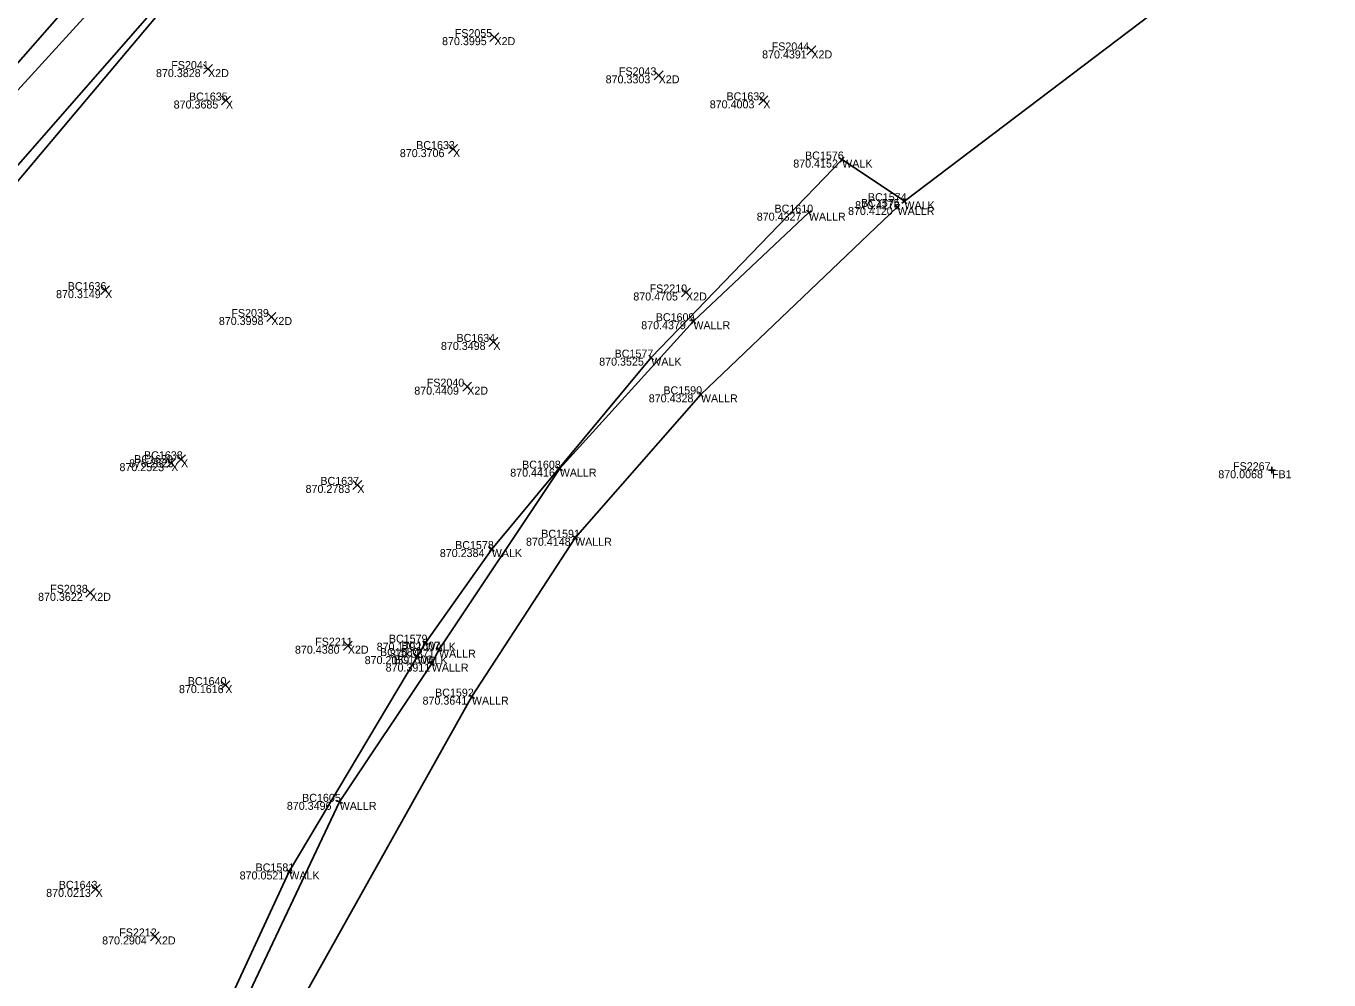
# Model space of a CAD drawing. Extents: x 1479425 to 1480294, y 379351 to 380102.
# Drawn here: x 1479701.41 to 1479711.18, y 379921.85 to 379929 of the extents above; entities that cross this region are included whole.
import ezdxf

# ---------------------------------------------------------------- set-up
doc = ezdxf.new("R2010")
doc.units = 0
for name, color, linetype in [('PV_X_Curb', 7, 'Continuous'), ('PV_X_Walk', 7, 'Continuous'), ('RD_X_Wall', 7, 'Continuous'), ('SV_X_Random_Point', 7, 'Continuous'), ('SV_X_Shot_Marker', 7, 'Continuous'), ('SV_X_Text_Comment', 7, 'Continuous'), ('SV_X_Text_Elevation', 7, 'Continuous'), ('SV_X_Text_Name', 7, 'Continuous')]:
    doc.layers.add(name, color=color, linetype=linetype)

msp = doc.modelspace()

# ---------------------------------------------------------------- linework, layer by layer
at = {"layer": 'PV_X_Curb'}
for points in [[(1479696.2636, 379903.5386), (1479695.5705, 379906.7461), (1479695.2973, 379909.3412), (1479695.1738, 379911.6458), (1479695.3654, 379914.6115), (1479695.6976, 379917.6668), (1479696.2624, 379919.5688), (1479696.9758, 379921.5611), (1479698.1082, 379924.2136), (1479700.2799, 379927.5011), (1479703.0248, 379930.6372), (1479705.9498, 379933.539), (1479706.9435, 379934.3789), (1479708.0749, 379934.8076), (1479711.183, 379937.5526), (1479719.99, 379942.1167), (1479736.739, 379950.5318), (1479753.296, 379958.795), (1479766.716, 379965.5627), (1479785.836, 379974.8289), (1479802.25, 379983.0541), (1479831.407, 379997.252)], [(1479714.5618, 379931.5973), (1479714.9536, 379931.8464), (1479713.9233, 379933.1457), (1479712.2808, 379934.1691), (1479710.4236, 379934.7733), (1479708.7692, 379934.7899), (1479708.1103, 379934.7976), (1479707.0655, 379934.2154), (1479706.4002, 379933.8431), (1479705.6821, 379933.0592), (1479703.0049, 379930.3348), (1479700.4209, 379927.5017), (1479698.1162, 379923.7926), (1479697.0539, 379921.4468), (1479696.3167, 379919.5129), (1479695.8109, 379917.6805), (1479695.4613, 379914.2655), (1479695.2919, 379911.6604), (1479695.2827, 379911.4711), (1479695.5098, 379908.7638), (1479695.6518, 379906.8062)], [(1479696.7341, 379903.7226), (1479696.0777, 379906.871), (1479695.8572, 379909.3669), (1479695.6789, 379911.5748), (1479695.6301, 379911.7177), (1479695.7295, 379913.104), (1479695.9783, 379915.6746), (1479696.1977, 379917.4938), (1479696.6417, 379919.3847), (1479697.4123, 379921.3734), (1479698.5912, 379923.9386), (1479699.838, 379926.0575), (1479700.67, 379927.1843), (1479703.3721, 379930.2685), (1479706.2512, 379933.0593), (1479706.6718, 379933.5352), (1479707.0448, 379933.7387), (1479707.4133, 379933.9238), (1479708.304, 379934.3327), (1479710.1486, 379934.3742), (1479711.6155, 379933.9308), (1479713.6212, 379932.8847), (1479714.2993, 379932.0346), (1479714.5618, 379931.5973)]]:
    msp.add_lwpolyline(points, dxfattribs=at)
at = {"layer": 'PV_X_Walk'}
msp.add_lwpolyline([(1479700.8191, 379927.2069), (1479702.5188, 379929.2278), (1479704.6321, 379931.3562), (1479706.478, 379933.0394), (1479706.4999, 379933.151), (1479707.2217, 379933.6773), (1479708.112, 379934.0884), (1479708.635, 379934.2846), (1479709.9955, 379934.2605), (1479711.7375, 379933.7876), (1479713.5401, 379932.634), (1479713.998, 379932.2143), (1479711.7035, 379930.4698), (1479709.8435, 379929.0857), (1479707.9993, 379927.6902), (1479707.5323, 379928.0023), (1479706.101, 379926.5176), (1479704.9058, 379925.0828), (1479704.4088, 379924.3811), (1479704.348, 379924.2805), (1479703.3879, 379922.6665), (1479702.6175, 379921.0036)], dxfattribs=at)
at = {"layer": 'RD_X_Wall'}
msp.add_lwpolyline([(1479707.9477, 379927.6468), (1479706.4736, 379926.2425), (1479705.5301, 379925.1676), (1479704.7565, 379923.9768), (1479703.514, 379921.7583), (1479702.6632, 379919.5789), (1479702.2332, 379917.4471), (1479702.0758, 379915.6878), (1479701.8768, 379912.6189), (1479701.5063, 379913.0175), (1479701.6342, 379915.7099), (1479701.6071, 379915.8229), (1479701.8518, 379917.8328), (1479702.3444, 379919.6609), (1479702.3531, 379919.8421), (1479703.0284, 379921.6293), (1479703.7656, 379923.1882), (1479704.4556, 379924.2246), (1479704.5099, 379924.3288), (1479705.4153, 379925.6855), (1479706.4172, 379926.7904), (1479707.2828, 379927.6042)], dxfattribs=at)
at = {"layer": 'SV_X_Random_Point'}
for p, q in [((1479704.8927, 379928.8862), (1479704.9593, 379928.953)), ((1479704.8927, 379928.953), (1479704.9593, 379928.8862)), ((1479707.2687, 379928.7866), (1479707.3353, 379928.8534)), ((1479707.2687, 379928.8534), (1479707.3353, 379928.7866)), ((1479702.7457, 379928.6467), (1479702.8123, 379928.7135)), ((1479702.7457, 379928.7135), (1479702.8123, 379928.6467)), ((1479706.1237, 379928.6), (1479706.1903, 379928.6668)), ((1479706.1237, 379928.6668), (1479706.1903, 379928.6)), ((1479702.8796, 379928.4111), (1479702.9462, 379928.4779)), ((1479702.8796, 379928.4779), (1479702.9462, 379928.4111)), ((1479706.9084, 379928.4127), (1479706.975, 379928.4795)), ((1479706.9084, 379928.4795), (1479706.975, 379928.4127)), ((1479704.5827, 379928.0471), (1479704.6493, 379928.1139)), ((1479704.5827, 379928.1139), (1479704.6493, 379928.0471)), ((1479701.9744, 379926.99), (1479702.041, 379927.0568)), ((1479701.9744, 379927.0568), (1479702.041, 379926.99)), ((1479706.3287, 379926.9725), (1479706.3953, 379927.0393)), ((1479706.3287, 379927.0393), (1479706.3953, 379926.9725)), ((1479703.2197, 379926.7888), (1479703.2863, 379926.8556)), ((1479703.2197, 379926.8556), (1479703.2863, 379926.7888)), ((1479704.8843, 379926.6019), (1479704.9509, 379926.6687)), ((1479704.8843, 379926.6687), (1479704.9509, 379926.6019)), ((1479704.6887, 379926.2668), (1479704.7553, 379926.3336)), ((1479704.6887, 379926.3336), (1479704.7553, 379926.2668)), ((1479702.4695, 379925.6933), (1479702.5361, 379925.7601)), ((1479702.4695, 379925.7601), (1479702.5361, 379925.6933)), ((1479702.5432, 379925.7224), (1479702.6098, 379925.7892)), ((1479702.5432, 379925.7892), (1479702.6098, 379925.7224)), ((1479703.8647, 379925.5302), (1479703.9313, 379925.597)), ((1479703.8647, 379925.597), (1479703.9313, 379925.5302)), ((1479701.8617, 379924.7214), (1479701.9283, 379924.7882)), ((1479701.8617, 379924.7882), (1479701.9283, 379924.7214)), ((1479703.7937, 379924.3253), (1479703.8603, 379924.3921)), ((1479703.7937, 379924.3921), (1479703.8603, 379924.3253)), ((1479702.8751, 379924.0296), (1479702.9417, 379924.0964)), ((1479702.8751, 379924.0964), (1479702.9417, 379924.0296)), ((1479701.903, 379922.5025), (1479701.9696, 379922.5693)), ((1479701.903, 379922.5693), (1479701.9696, 379922.5025)), ((1479702.3467, 379922.146), (1479702.4133, 379922.2128)), ((1479702.3467, 379922.2128), (1479702.4133, 379922.146))]:
    msp.add_line(p, q, dxfattribs=at)
at = {"layer": 'SV_X_Shot_Marker'}
for p, q in [((1479707.5531, 379927.9884), (1479707.5115, 379928.0162)), ((1479707.5184, 379927.9815), (1479707.5462, 379928.0231)), ((1479707.5323, 379928.0023), (1479707.5323, 379928.0023)), ((1479707.9658, 379927.6641), (1479707.9296, 379927.6296)), ((1479707.9649, 379927.6287), (1479707.9305, 379927.6649)), ((1479708.0192, 379927.7053), (1479707.9794, 379927.6751)), ((1479708.0144, 379927.6703), (1479707.9842, 379927.7102)), ((1479707.9993, 379927.6902), (1479707.9993, 379927.6902)), ((1479707.2646, 379927.5871), (1479707.301, 379927.6213)), ((1479707.2657, 379927.6224), (1479707.2999, 379927.586)), ((1479707.2828, 379927.6042), (1479707.2828, 379927.6042)), ((1479707.9477, 379927.6468), (1479707.9477, 379927.6468)), ((1479706.3987, 379926.8072), (1479706.4357, 379926.7736)), ((1479706.4004, 379926.7719), (1479706.434, 379926.8089)), ((1479706.4172, 379926.7904), (1479706.4172, 379926.7904)), ((1479706.119, 379926.5003), (1479706.083, 379926.535)), ((1479706.1183, 379926.5356), (1479706.0836, 379926.4996)), ((1479706.101, 379926.5176), (1479706.101, 379926.5176)), ((1479706.4917, 379926.2598), (1479706.4555, 379926.2253)), ((1479706.4908, 379926.2244), (1479706.4564, 379926.2606)), ((1479706.4736, 379926.2425), (1479706.4736, 379926.2425)), ((1479705.4014, 379925.6647), (1479705.4292, 379925.7063)), ((1479705.3945, 379925.6994), (1479705.4361, 379925.6716)), ((1479705.4153, 379925.6855), (1479705.4153, 379925.6855)), ((1479710.73, 379925.6737), (1479710.78, 379925.6737)), ((1479710.755, 379925.6987), (1479710.755, 379925.6487)), ((1479710.755, 379925.6737), (1479710.755, 379925.6737)), ((1479705.5489, 379925.1511), (1479705.5113, 379925.1841)), ((1479705.5466, 379925.1864), (1479705.5136, 379925.1488)), ((1479705.5301, 379925.1676), (1479705.5301, 379925.1676)), ((1479704.925, 379925.0668), (1479704.8866, 379925.0988)), ((1479704.9218, 379925.102), (1479704.8898, 379925.0636)), ((1479704.9058, 379925.0828), (1479704.9058, 379925.0828)), ((1479704.4292, 379924.3667), (1479704.3884, 379924.3956)), ((1479704.4232, 379924.4015), (1479704.3943, 379924.3607)), ((1479704.4088, 379924.3811), (1479704.4088, 379924.3811)), ((1479704.4877, 379924.3404), (1479704.5321, 379924.3173)), ((1479704.4983, 379924.3066), (1479704.5214, 379924.351)), ((1479704.3694, 379924.2676), (1479704.3266, 379924.2935)), ((1479704.3609, 379924.3019), (1479704.3351, 379924.2591)), ((1479704.348, 379924.2805), (1479704.348, 379924.2805)), ((1479704.4417, 379924.2038), (1479704.4695, 379924.2454)), ((1479704.5099, 379924.3288), (1479704.5099, 379924.3288)), ((1479704.4348, 379924.2385), (1479704.4764, 379924.2108)), ((1479704.4556, 379924.2246), (1479704.4556, 379924.2246)), ((1479704.7775, 379923.9632), (1479704.7355, 379923.9904)), ((1479704.7701, 379923.9978), (1479704.7429, 379923.9559)), ((1479704.7565, 379923.9768), (1479704.7565, 379923.9768)), ((1479703.743, 379923.1989), (1479703.7882, 379923.1775)), ((1479703.7549, 379923.1656), (1479703.7763, 379923.2108)), ((1479703.7656, 379923.1882), (1479703.7656, 379923.1882)), ((1479703.4094, 379922.6537), (1479703.3664, 379922.6793)), ((1479703.4007, 379922.688), (1479703.3751, 379922.645)), ((1479703.3879, 379922.6665), (1479703.3879, 379922.6665))]:
    msp.add_line(p, q, dxfattribs=at)

# ---------------------------------------------------------------- texts
at = {"layer": 'SV_X_Text_Comment'}
for s, p in [('X2D', (1479704.926, 379928.8596)), ('X2D', (1479707.302, 379928.76)), ('X2D', (1479702.779, 379928.6201)), ('X2D', (1479706.157, 379928.5734)), ('X', (1479702.9129, 379928.3845)), ('X', (1479706.9417, 379928.3861)), ('X', (1479704.616, 379928.0205)), ('WALK', (1479707.5323, 379927.9423)), ('WALK', (1479707.9993, 379927.6302)), ('WALLR', (1479707.2828, 379927.5442)), ('WALLR', (1479707.9477, 379927.5868)), ('X', (1479702.0077, 379926.9634)), ('X2D', (1479706.362, 379926.9459)), ('X2D', (1479703.253, 379926.7622)), ('WALLR', (1479706.4172, 379926.7304)), ('X', (1479704.9176, 379926.5753)), ('WALK', (1479706.101, 379926.4576)), ('X2D', (1479704.722, 379926.2402)), ('WALLR', (1479706.4736, 379926.1825)), ('X', (1479702.5028, 379925.6667)), ('X', (1479702.5765, 379925.6958)), ('WALLR', (1479705.4153, 379925.6255)), ('FB1', (1479710.755, 379925.6137)), ('X', (1479703.898, 379925.5036)), ('WALLR', (1479705.5301, 379925.1076)), ('WALK', (1479704.9058, 379925.0228)), ('X2D', (1479701.895, 379924.6948)), ('X2D', (1479703.827, 379924.2987)), ('WALK', (1479704.4088, 379924.3211)), ('WALK', (1479704.348, 379924.2205)), ('WALLR', (1479704.5099, 379924.2688)), ('WALLR', (1479704.4556, 379924.1646)), ('X', (1479702.9084, 379924.003)), ('WALLR', (1479704.7565, 379923.9168)), ('WALLR', (1479703.7656, 379923.1282)), ('WALK', (1479703.3879, 379922.6065)), ('X', (1479701.9363, 379922.4759)), ('X2D', (1479702.38, 379922.1194))]:
    msp.add_text(s, height=0.06, dxfattribs=at).set_placement(p)
at = {"layer": 'SV_X_Text_Elevation'}
for s, p in [('870.3995', (1479704.5334, 379928.8596)), ('870.4391', (1479706.9325, 379928.76)), ('870.3828', (1479702.3888, 379928.6201)), ('870.3303', (1479705.7597, 379928.5734)), ('870.3685', (1479702.5213, 379928.3845)), ('870.4003', (1479706.5402, 379928.3861)), ('870.3706', (1479704.2168, 379928.0205)), ('870.4152', (1479707.1662, 379927.9423)), ('870.4176', (1479707.6299, 379927.6302)), ('870.4327', (1479706.8926, 379927.5442)), ('870.4120', (1479707.5769, 379927.5868)), ('870.3149', (1479701.6397, 379926.9634)), ('870.4705', (1479705.9671, 379926.9459)), ('870.3998', (1479702.8599, 379926.7622)), ('870.4379', (1479706.0265, 379926.7304)), ('870.3498', (1479704.525, 379926.5753)), ('870.3525', (1479705.7113, 379926.4576)), ('870.4409', (1479704.3252, 379926.2402)), ('870.4328', (1479706.0829, 379926.1825)), ('870.2523', (1479702.1149, 379925.6667)), ('870.2625', (1479702.1877, 379925.6958)), ('870.4416', (1479705.0445, 379925.6255)), ('870.0068', (1479710.3525, 379925.6137)), ('870.2783', (1479703.5101, 379925.5036)), ('870.4148', (1479705.1626, 379925.1076)), ('870.2384', (1479704.5165, 379925.0228)), ('870.3622', (1479701.5048, 379924.6948)), ('870.4380', (1479703.4306, 379924.2987)), ('870.1792', (1479704.0432, 379924.3211)), ('870.2059', (1479703.9531, 379924.2205)), ('870.3871', (1479704.1427, 379924.2688)), ('870.3911', (1479704.1102, 379924.1646)), ('870.1616', (1479702.5612, 379924.003)), ('870.3641', (1479704.387, 379923.9168)), ('870.3496', (1479703.3697, 379923.1282)), ('870.0521', (1479703.016, 379922.6065)), ('870.0213', (1479701.5655, 379922.4759)), ('870.2904', (1479701.9851, 379922.1194))]:
    msp.add_text(s, height=0.06, dxfattribs=at).set_placement(p)
at = {"layer": 'SV_X_Text_Name'}
for s, p in [('FS2055', (1479704.6284, 379928.9196)), ('FS2044', (1479707.0044, 379928.82)), ('FS2041', (1479702.5035, 379928.6801)), ('FS2043', (1479705.8589, 379928.6334)), ('BC1635', (1479702.6361, 379928.4445)), ('BC1632', (1479706.6654, 379928.4461)), ('BC1633', (1479704.3392, 379928.0805)), ('BC1576', (1479707.2546, 379928.0023)), ('BC1610', (1479707.0254, 379927.6042)), ('BC1575', (1479707.6737, 379927.6468)), ('BC1574', (1479707.7258, 379927.6902)), ('BC1636', (1479701.7271, 379927.0234)), ('FS2210', (1479706.0894, 379927.0059)), ('FS2039', (1479702.954, 379926.8222)), ('BC1609', (1479706.1352, 379926.7904)), ('BC1634', (1479704.6413, 379926.6353)), ('BC1577', (1479705.827, 379926.5176)), ('FS2040', (1479704.4187, 379926.3002)), ('BC1590', (1479706.1925, 379926.2425)), ('BC1638', (1479702.2992, 379925.7558)), ('BC1639', (1479702.2255, 379925.7267)), ('BC1608', (1479705.1333, 379925.6855)), ('FS2267', (1479710.4631, 379925.6737)), ('BC1637', (1479703.6212, 379925.5636)), ('BC1591', (1479705.2768, 379925.1676)), ('BC1578', (1479704.6314, 379925.0828)), ('FS2038', (1479701.596, 379924.7548)), ('BC1579', (1479704.1344, 379924.3811)), ('FS2211', (1479703.5822, 379924.3587)), ('BC1580', (1479704.0679, 379924.2805)), ('BC1607', (1479704.2284, 379924.3288)), ('BC1606', (1479704.1703, 379924.2246)), ('BC1640', (1479702.6269, 379924.063)), ('BC1592', (1479704.4811, 379923.9768)), ('BC1605', (1479703.4841, 379923.1882)), ('BC1581', (1479703.1355, 379922.6665)), ('BC1643', (1479701.66, 379922.5359)), ('FS2212', (1479702.1131, 379922.1794))]:
    msp.add_text(s, height=0.06, dxfattribs=at).set_placement(p)

doc.saveas('drawing.dxf')
